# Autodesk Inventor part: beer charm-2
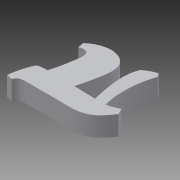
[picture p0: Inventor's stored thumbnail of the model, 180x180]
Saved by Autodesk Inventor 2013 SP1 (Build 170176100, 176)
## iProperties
Created: 2013-02
Part Number: beer charm-2
Material: Generic
Document SubType Name: Modeling
Designer: Will McDonald
Density: 1 g/cm^3
Mass: 1.28607 g
Surface Area: 10.73 cm^2
Volume: 1.28607 cm^3
Author: Will McDonald
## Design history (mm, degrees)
sketch "Sketch1"
  geometry: L1 (4.054, -21.485)-(4.747, -22.491); L2 (4.747, -22.491)-(5.66, -22.17); L3 (5.66, -22.17)-(6.723, -21.692); L4 (6.723, -21.692)-(7.871, -20.808); L5 (7.871, -20.808)-(8.338, -19.684); L6 (8.338, -19.684)-(9.559, -16.781); L7 (9.559, -16.781)-(7.089, -7.563); L8 (7.109, -7.635)-(7.089, -7.563); L9 (7.089, -7.563)-(4.56, -8.165); L10 (4.56, -8.165)-(5.492, -11.643); L11 (5.492, -11.643)-(5.701, -16.585); L12 (5.701, -16.585)-(4.054, -21.485); L13 (22.506, -8.247)-(23.138, -7.43); L14 (23.138, -7.43)-(24.103, -4.125); L15 (24.103, -4.125)-(24.214, -2.195); L16 (24.214, -2.195)-(22.729, -1.897); L17 (22.729, -1.897)-(22.209, -2.9); L18 (22.209, -2.9)-(21.689, -3.197); L19 (21.689, -3.197)-(20.278, -3.197); L20 (20.278, -3.197)-(16.565, -3.197); L21 (16.565, -3.197)-(12.258, -3.197); L22 (12.258, -3.197)-(8.805, -3.123); L23 (8.805, -3.123)-(3.718, -3.049); L24 (3.718, -3.049)-(2.195, -5.87); L25 (2.195, -5.87)-(0.747, -7.913); L26 (0.747, -7.913)-(1.527, -9.509); L27 (1.527, -9.509)-(3.532, -8.433); L28 (3.532, -8.433)-(4.534, -8.284); L29 (4.534, -8.284)-(6.688, -8.321); L30 (6.688, -8.321)-(9.287, -8.395); L31 (9.287, -8.395)-(10.735, -8.395); L32 (10.735, -8.395)-(11.293, -8.507); L33 (11.293, -8.507)-(13.149, -8.47); L34 (13.149, -8.47)-(20.093, -8.581); L35 (20.093, -8.581)-(21.021, -8.581); L36 (21.021, -8.581)-(21.838, -8.507); L37 (21.838, -8.507)-(22.506, -8.247); L38 (19.572, -18.094)-(18.877, -17.972); L39 (18.877, -17.972)-(18.286, -17.264); L40 (18.286, -17.264)-(18.726, -14.552); L41 (18.726, -14.552)-(19.16, -11.875); L42 (19.16, -11.875)-(19.289, -11.144); L43 (19.289, -11.144)-(20.023, -8.484); L44 (20.023, -8.484)-(13.204, -7.168); L45 (13.204, -7.168)-(12.55, -9.805); L46 (12.55, -9.805)-(12.122, -11.162); L47 (12.122, -11.162)-(11.471, -14.856); L48 (11.471, -14.856)-(10.871, -18.257); L49 (13.469, -21.166)-(15.389, -21.504); L50 (15.389, -21.504)-(17.546, -21.884); L51 (17.546, -21.884)-(20.207, -20.695); L52 (20.207, -20.695)-(21.489, -19.412); L53 (21.489, -19.412)-(21.228, -17.896); L54 (21.228, -17.896)-(20.598, -18.049); L55 (20.598, -18.049)-(20.157, -18.198); L56 (20.157, -18.198)-(19.572, -18.094); L57 (10.871, -18.257)-(11.75, -20.222); L58 (11.75, -20.222)-(13.469, -21.166); 5 further points
  constraints: 18 end point, 3 point on line, 50 other
extrude "Extrusion1" new body sketch "Sketch1" distance "d0" = 5.08; taper "d1" = 0 deg
fillet "Fillet1" dims "d2" = 0.635
body "Solid1"
